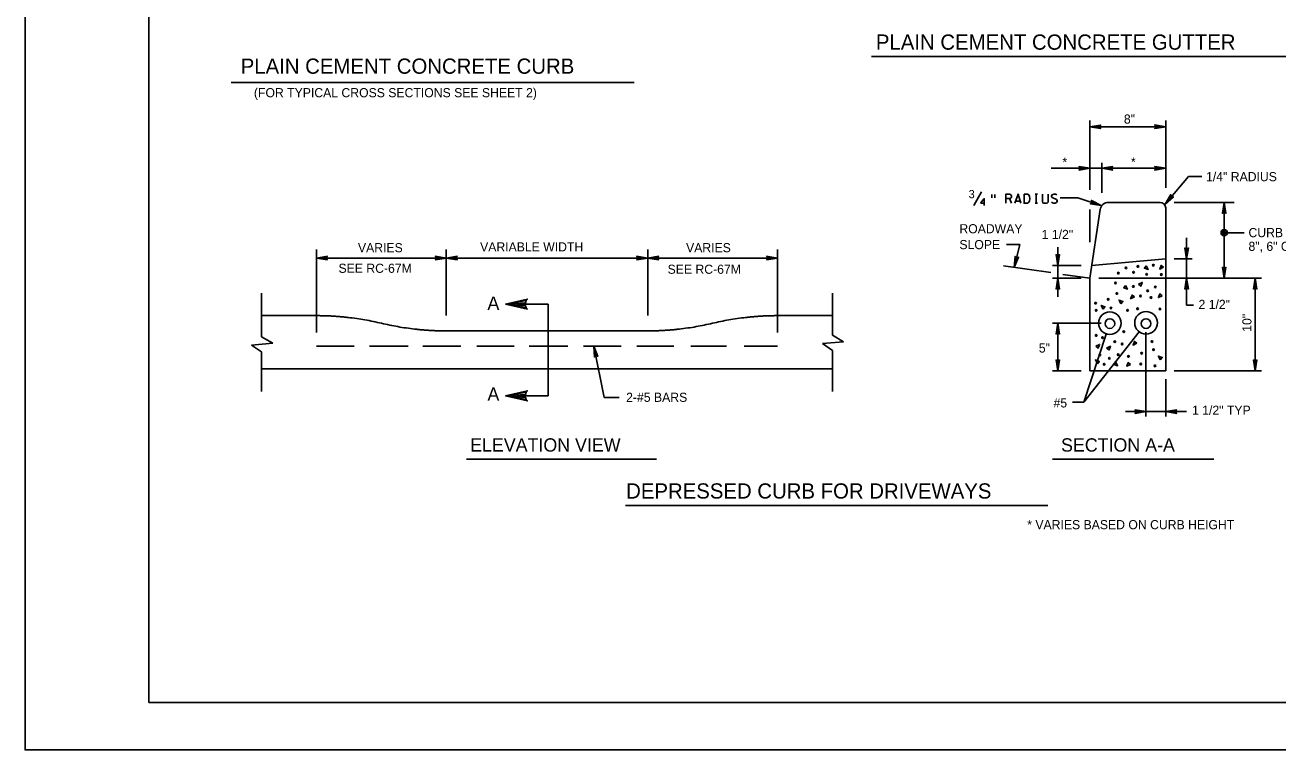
# Model space of a CAD drawing. Extents: x 2092490 to 2102560, y 980575 to 982524.
# Drawn here: x 2096834 to 2098130, y 980575 to 981325 of the extents above; entities that cross this region are included whole.
import ezdxf

# ---------------------------------------------------------------- set-up
doc = ezdxf.new("R2010")
doc.units = 0
for name, color, linetype in [('1', 7, 'Continuous'), ('2', 7, 'Continuous'), ('3', 7, 'Continuous'), ('57', 7, 'Continuous'), ('PLT-BNDY', 7, 'Continuous')]:
    doc.layers.add(name, color=color, linetype=linetype)

msp = doc.modelspace()

# ---------------------------------------------------------------- linework, layer by layer
at = {"layer": '1'}
for p, q in [((2096962.1, 982474.5), (2096962.1, 980624.1)), ((2097929.4, 980934.9), (2097986.7, 981007.6)), ((2097952.7, 981005.3), (2097929.4, 980934.9)), ((2096962.1, 980624.1), (2099540.8, 980624.1))]:
    msp.add_line(p, q, dxfattribs=at)
for centre, radius in [((2097956.4, 981016.5), 11.7), ((2097956.5, 981016.1), 5.02), ((2097993.9, 981016.9), 11.7), ((2097993.9, 981016.1), 5.02)]:
    msp.add_circle(centre, radius, dxfattribs=at)
at = {"layer": '2'}
for p, q in [((2097935.8, 981063.1), (2097946.4, 981134.1)), ((2098008.5, 981141.5), (2097955, 981141.5)), ((2098014.3, 980967.2), (2098014.3, 981135.7)), ((2098014.3, 981083), (2097937.8, 981076.1)), ((2097935.8, 980967.2), (2097935.8, 981063.1)), ((2097078.8, 981002.4), (2097078.8, 981047.6)), ((2097669.4, 981004.1), (2097669.4, 981047.6)), ((2097078.8, 981024.3), (2097135.6, 981024.3)), ((2097612.6, 981024.3), (2097669.4, 981024.3)), ((2097269.9, 981008.5), (2097478.3, 981008.5)), ((2097680.9, 980997.3), (2097669.4, 981004.1)), ((2097068.5, 980993.7), (2097090.4, 980995.7)), ((2097078.8, 980986.8), (2097068.5, 980993.7)), ((2097090.4, 980995.7), (2097078.8, 981002.4)), ((2097135.6, 980992.8), (2097174.7, 980992.8)), ((2097190.5, 980992.8), (2097230.6, 980992.8)), ((2097245.6, 980992.8), (2097284.9, 980992.8)), ((2097301.5, 980992.8), (2097340.2, 980992.8)), ((2097355.6, 980992.8), (2097395.7, 980992.8)), ((2097411.9, 980992.8), (2097450.8, 980992.8)), ((2097467, 980992.8), (2097505.5, 980992.8)), ((2097522.9, 980992.8), (2097559.8, 980992.8)), ((2097578, 980992.8), (2097612.6, 980992.8)), ((2097659.1, 980995.3), (2097680.9, 980997.3)), ((2097669.4, 980988.4), (2097659.1, 980995.3)), ((2097078.8, 980945.8), (2097078.8, 980986.8)), ((2097669.4, 980945.8), (2097669.4, 980988.4)), ((2097078.8, 980969.2), (2097669.4, 980969.2)), ((2098014.3, 980967.2), (2097935.8, 980967.2))]:
    msp.add_line(p, q, dxfattribs=at)
for centre, radius, start, end in [((2097955, 981132.8), 8.72, 90, 171.5668), ((2098008.5, 981135.7), 5.81, 0, 90)]:
    msp.add_arc(centre, radius, start, end, dxfattribs=at)
for points in [[(2097269.9, 981008.5), (2097236.4, 981008.5), (2097169.2, 981024.3), (2097135.6, 981024.3)], [(2097478.3, 981008.5), (2097511.8, 981008.5), (2097579, 981024.3), (2097612.6, 981024.3)]]:
    msp.add_open_spline(points, degree=2, dxfattribs=at)
at = {"layer": '3'}
for p, q in [((2098154.2, 981292.5), (2097710, 981292.5)), ((2097047.3, 981265.6), (2097464.2, 981265.6)), ((2097935.8, 981154.4), (2097935.8, 981226.2)), ((2098014.3, 981156.4), (2098014.3, 981226.2)), ((2098014.3, 981219.8), (2097935.8, 981219.8)), ((2097895.6, 981176.8), (2097948.1, 981176.8)), ((2097948.1, 981151.5), (2097948.1, 981182.4)), ((2097948.1, 981176.8), (2098014.3, 981176.8)), ((2098013.6, 981139.8), (2098037.8, 981168.2)), ((2098037.8, 981168.2), (2098051.5, 981168.2)), ((2097905.2, 981146.3), (2097923.5, 981146.3)), ((2097923.5, 981146.3), (2097947.5, 981138.2)), ((2097935.8, 981100.5), (2097935.8, 981134.1)), ((2098022.9, 981141.5), (2098085, 981141.5)), ((2098074.8, 981063.1), (2098074.8, 981141.5)), ((2098074.8, 981110.1), (2098095.5, 981110.1)), ((2097863.3, 981098), (2097849.4, 981098)), ((2097857.6, 981074.2), (2097863.3, 981098)), ((2097902.7, 981095.2), (2097902.7, 981076.1)), ((2098035.9, 981083), (2098035.9, 981104.9)), ((2097135.6, 981007), (2097135.6, 981092.6)), ((2097269.9, 981083.9), (2097135.6, 981083.9)), ((2097269.9, 981024.3), (2097269.9, 981092.6)), ((2097478.3, 981083.9), (2097269.9, 981083.9)), ((2097478.3, 981024.3), (2097478.3, 981092.6)), ((2097478.3, 981083.9), (2097612.6, 981083.9)), ((2097612.6, 981007), (2097612.6, 981092.6)), ((2098022.9, 981083), (2098041.6, 981083)), ((2098035.9, 981035.2), (2098035.9, 981083)), ((2097895.3, 981068.8), (2097846.5, 981075.7)), ((2097926.9, 981076.1), (2097897.2, 981076.1)), ((2097902.7, 981076.1), (2097902.7, 981043.7)), ((2097926.9, 981063.1), (2097897.2, 981063.1)), ((2097935.8, 981063.1), (2097907.8, 981067)), ((2098113.3, 981063.1), (2097944.9, 981063.1)), ((2098106.8, 980967.2), (2098106.8, 981063.1)), ((2097342.6, 981036.2), (2097375.3, 981036.2)), ((2097375.3, 980941.3), (2097375.3, 981036.2)), ((2098035.9, 981035.2), (2098043, 981035.2)), ((2097947.4, 981016.5), (2097897.2, 981016.5)), ((2097902.7, 981016.5), (2097902.7, 980967.2)), ((2097993.8, 981007.2), (2097993.8, 980920.1)), ((2097433.4, 980939.6), (2097422.6, 980992.8)), ((2097926.9, 980967.2), (2097897.2, 980967.2)), ((2098022.9, 980967.2), (2098113.3, 980967.2)), ((2098014.3, 980958.6), (2098014.3, 980920.1)), ((2097342.6, 980941.3), (2097375.3, 980941.3)), ((2097433.4, 980939.6), (2097448.9, 980939.6)), ((2097917.7, 980934.9), (2097929.4, 980934.9)), ((2097972.6, 980925), (2098014.3, 980925)), ((2098014.3, 980925), (2098035.9, 980925)), ((2097290.9, 980875.9), (2097487.5, 980875.9)), ((2097897, 980875.9), (2098063.9, 980875.9)), ((2097455.3, 980827.9), (2097892.4, 980827.9))]:
    msp.add_line(p, q, dxfattribs=at)
for points in [[(2097946.6, 981218.4), (2097946.2, 981219.2), (2097935.8, 981219.8), (2097946.6, 981218.4), (2097947.1, 981217.9), (2097935.8, 981219.8), (2097946.1, 981220.3), (2097946.5, 981221), (2097935.8, 981219.8), (2097947.1, 981221.5), (2097946.5, 981221)], [(2098003.5, 981221.1), (2098003.9, 981220.3), (2098014.3, 981219.8), (2098003.5, 981221.1), (2098003, 981221.6), (2098014.3, 981219.8), (2098004, 981219.2), (2098003.6, 981218.5), (2098014.3, 981219.8), (2098003, 981218), (2098003.6, 981218.5)], [(2097925.1, 981178.1), (2097925.5, 981177.3), (2097935.8, 981176.8), (2097925.1, 981178.1), (2097924.6, 981178.6), (2097935.8, 981176.8), (2097925.5, 981176.3), (2097925.1, 981175.5), (2097935.8, 981176.8), (2097924.6, 981175), (2097925.1, 981175.5)], [(2097958.9, 981175.4), (2097958.5, 981176.2), (2097948.1, 981176.8), (2097958.9, 981175.4), (2097959.4, 981175), (2097948.1, 981176.8), (2097958.4, 981177.3), (2097958.8, 981178), (2097948.1, 981176.8), (2097959.4, 981178.6), (2097958.8, 981178)], [(2098003.5, 981175.4), (2098003.9, 981176.2), (2098014.3, 981176.8), (2098003.5, 981175.4), (2098003, 981175), (2098014.3, 981176.8), (2098004, 981177.3), (2098003.6, 981178), (2098014.3, 981176.8), (2098003, 981178.6), (2098003.6, 981178)], [(2097815.6, 981138.1), (2097823.7, 981152.3)], [(2097834.5, 981146.1), (2097834.5, 981149.5)], [(2097837.5, 981146.1), (2097837.5, 981149.5)], [(2097848.9, 981140.6), (2097848.9, 981150), (2097852.7, 981150), (2097853.8, 981149.7), (2097854.8, 981148.2), (2097854.8, 981147.3), (2097853.9, 981145.8), (2097852.7, 981145.4), (2097848.9, 981145.4)], [(2097858.3, 981140.6), (2097861.5, 981150), (2097864.5, 981140.6)], [(2097867.8, 981150), (2097871.2, 981150), (2097872.5, 981149.4), (2097873.3, 981147.7), (2097873.7, 981145.6), (2097873.2, 981142.9), (2097872.4, 981141.3), (2097871.2, 981140.6), (2097867.8, 981140.6), (2097867.8, 981150)], [(2097879.3, 981150), (2097881.5, 981150)], [(2097880.4, 981140.6), (2097880.4, 981150)], [(2097886.7, 981150), (2097886.7, 981142.5), (2097887, 981141.2), (2097888.3, 981140.6), (2097890.8, 981140.6), (2097892.2, 981141.2), (2097892.6, 981142.5), (2097892.6, 981150)], [(2097901.6, 981149.4), (2097900.1, 981150), (2097898.4, 981150), (2097896.8, 981149.4), (2097896.1, 981148.2), (2097896.1, 981147.7), (2097896.9, 981146.6), (2097901.2, 981144.4), (2097901.9, 981143.4), (2097901.9, 981142.5), (2097901.2, 981141.3), (2097899.9, 981140.6), (2097898.1, 981140.6), (2097897.3, 981140.9), (2097896.1, 981141.7)], [(2098021.6, 981147.1), (2098020.7, 981147.3), (2098013.6, 981139.8), (2098021.6, 981147.1), (2098022.3, 981147.2), (2098013.6, 981139.8), (2098019.9, 981148), (2098019.5, 981148.8), (2098013.6, 981139.8), (2098019.5, 981149.5), (2098019.5, 981148.8)], [(2097827, 981140.7), (2097823, 981140.7), (2097823, 981141), (2097826.1, 981145.3), (2097826.5, 981145.3), (2097826.5, 981138.2)], [(2097854.8, 981140.6), (2097852.6, 981145.4)], [(2097859.1, 981142.8), (2097863.8, 981142.8)], [(2097879.3, 981140.6), (2097881.5, 981140.6)], [(2097937.8, 981142.9), (2097937.9, 981142), (2097947.5, 981138.2), (2097937.8, 981142.9), (2097937.4, 981143.5), (2097947.5, 981138.2), (2097937.6, 981141), (2097937, 981140.4), (2097947.5, 981138.2), (2097936.3, 981140.1), (2097937, 981140.4)], [(2098073.5, 981130.8), (2098074.3, 981131.2), (2098074.8, 981141.5), (2098073.5, 981130.8), (2098073, 981130.2), (2098074.8, 981141.5), (2098075.3, 981131.2), (2098076.1, 981130.8), (2098074.8, 981141.5), (2098076.6, 981130.2), (2098076.1, 981130.8)], [(2098037.2, 981093.8), (2098036.5, 981093.4), (2098035.9, 981083), (2098037.2, 981093.8), (2098037.7, 981094.3), (2098035.9, 981083), (2098035.4, 981093.4), (2098034.6, 981093.7), (2098035.9, 981083), (2098034.1, 981094.3), (2098034.6, 981093.7)], [(2097146.4, 981082.6), (2097146, 981083.3), (2097135.6, 981083.9), (2097146.4, 981082.6), (2097146.9, 981082.1), (2097135.6, 981083.9), (2097146, 981084.4), (2097146.3, 981085.2), (2097135.6, 981083.9), (2097146.9, 981085.7), (2097146.3, 981085.2)], [(2097259.2, 981085.2), (2097259.6, 981084.5), (2097269.9, 981083.9), (2097259.2, 981085.2), (2097258.7, 981085.7), (2097269.9, 981083.9), (2097259.6, 981083.4), (2097259.2, 981082.6), (2097269.9, 981083.9), (2097258.7, 981082.1), (2097259.2, 981082.6)], [(2097280.7, 981082.6), (2097280.3, 981083.3), (2097269.9, 981083.9), (2097280.7, 981082.6), (2097281.2, 981082.1), (2097269.9, 981083.9), (2097280.3, 981084.4), (2097280.6, 981085.2), (2097269.9, 981083.9), (2097281.2, 981085.7), (2097280.6, 981085.2)], [(2097467.5, 981085.2), (2097467.9, 981084.5), (2097478.3, 981083.9), (2097467.5, 981085.2), (2097467, 981085.7), (2097478.3, 981083.9), (2097468, 981083.4), (2097467.6, 981082.6), (2097478.3, 981083.9), (2097467, 981082.1), (2097467.6, 981082.6)], [(2097489, 981082.6), (2097488.6, 981083.3), (2097478.3, 981083.9), (2097489, 981082.6), (2097489.5, 981082.1), (2097478.3, 981083.9), (2097488.6, 981084.4), (2097489, 981085.2), (2097478.3, 981083.9), (2097489.5, 981085.7), (2097489, 981085.2)], [(2097601.8, 981085.2), (2097602.2, 981084.5), (2097612.6, 981083.9), (2097601.8, 981085.2), (2097601.3, 981085.7), (2097612.6, 981083.9), (2097602.3, 981083.4), (2097601.9, 981082.6), (2097612.6, 981083.9), (2097601.3, 981082.1), (2097601.9, 981082.6)], [(2097861.4, 981084.3), (2097860.6, 981084.1), (2097857.6, 981074.2), (2097861.4, 981084.3), (2097862, 981084.7), (2097857.6, 981074.2), (2097859.5, 981084.3), (2097858.8, 981084.9), (2097857.6, 981074.2), (2097858.5, 981085.6), (2097858.8, 981084.9)], [(2097904.1, 981086.8), (2097903.3, 981086.4), (2097902.7, 981076.1), (2097904.1, 981086.8), (2097904.5, 981087.4), (2097902.7, 981076.1), (2097902.2, 981086.4), (2097901.4, 981086.8), (2097902.7, 981076.1), (2097900.9, 981087.4), (2097901.4, 981086.8)], [(2098076.2, 981073.8), (2098075.4, 981073.4), (2098074.8, 981063.1), (2098076.2, 981073.8), (2098076.6, 981074.3), (2098074.8, 981063.1), (2098074.3, 981073.4), (2098073.5, 981073.8), (2098074.8, 981063.1), (2098073, 981074.3), (2098073.5, 981073.8)], [(2097901.4, 981052.3), (2097902.1, 981052.7), (2097902.7, 981063.1), (2097901.4, 981052.3), (2097900.9, 981051.8), (2097902.7, 981063.1), (2097903.2, 981052.7), (2097904, 981052.4), (2097902.7, 981063.1), (2097904.5, 981051.8), (2097904, 981052.4)], [(2098034.5, 981052.3), (2098035.3, 981052.7), (2098035.9, 981063.1), (2098034.5, 981052.3), (2098034.1, 981051.8), (2098035.9, 981063.1), (2098036.4, 981052.7), (2098037.2, 981052.4), (2098035.9, 981063.1), (2098037.7, 981051.8), (2098037.2, 981052.4)], [(2098105.5, 981052.3), (2098106.3, 981052.7), (2098106.8, 981063.1), (2098105.5, 981052.3), (2098105, 981051.8), (2098106.8, 981063.1), (2098107.3, 981052.7), (2098108.1, 981052.4), (2098106.8, 981063.1), (2098108.6, 981051.8), (2098108.1, 981052.4)], [(2097352.7, 981032.3), (2097351.9, 981034.6), (2097331.3, 981036.2), (2097352.7, 981032.3), (2097353.8, 981031), (2097331.3, 981036.2), (2097351.9, 981037.7), (2097352.7, 981039.9), (2097331.3, 981036.2), (2097353.8, 981041.4), (2097352.7, 981039.9)], [(2097901.4, 981005.7), (2097902.1, 981006.1), (2097902.7, 981016.5), (2097901.4, 981005.7), (2097900.9, 981005.2), (2097902.7, 981016.5), (2097903.2, 981006.1), (2097904, 981005.8), (2097902.7, 981016.5), (2097904.5, 981005.2), (2097904, 981005.8)], [(2097423.4, 980982), (2097424.1, 980982.6), (2097422.6, 980992.8), (2097423.4, 980982), (2097423.1, 980981.4), (2097422.6, 980992.8), (2097425.1, 980982.8), (2097426, 980982.6), (2097422.6, 980992.8), (2097426.6, 980982.1), (2097426, 980982.6)], [(2097904.1, 980977.9), (2097903.3, 980977.5), (2097902.7, 980967.2), (2097904.1, 980977.9), (2097904.5, 980978.5), (2097902.7, 980967.2), (2097902.2, 980977.5), (2097901.4, 980977.9), (2097902.7, 980967.2), (2097900.9, 980978.5), (2097901.4, 980977.9)], [(2098108.2, 980977.9), (2098107.4, 980977.5), (2098106.8, 980967.2), (2098108.2, 980977.9), (2098108.6, 980978.5), (2098106.8, 980967.2), (2098106.3, 980977.5), (2098105.5, 980977.9), (2098106.8, 980967.2), (2098105, 980978.5), (2098105.5, 980977.9)], [(2097352.7, 980937.5), (2097351.9, 980939.7), (2097331.3, 980941.3), (2097352.7, 980937.5), (2097353.8, 980936.1), (2097331.3, 980941.3), (2097351.9, 980942.8), (2097352.7, 980945), (2097331.3, 980941.3), (2097353.8, 980946.5), (2097352.7, 980945)], [(2097983, 980926.4), (2097983.4, 980925.6), (2097993.8, 980925), (2097983, 980926.4), (2097982.5, 980926.8), (2097993.8, 980925), (2097983.4, 980924.5), (2097983.1, 980923.7), (2097993.8, 980925), (2097982.5, 980923.2), (2097983.1, 980923.7)], [(2098025, 980923.7), (2098024.6, 980924.5), (2098014.3, 980925), (2098025, 980923.7), (2098025.5, 980923.2), (2098014.3, 980925), (2098024.6, 980925.5), (2098025, 980926.3), (2098014.3, 980925), (2098025.5, 980926.8), (2098025, 980926.3)]]:
    msp.add_lwpolyline(points, dxfattribs=at)
for radius in [3.28, 1.64]:
    msp.add_circle((2098074.8, 981110.1), radius, dxfattribs=at)
at = {"layer": '57'}
for points in [[(2097994.1, 981075.8), (2097992.2, 981073.3), (2097996, 981071.9)], [(2098012, 981074.3), (2098009.5, 981076.3), (2098008.1, 981072.4)], [(2097972.8, 981055.6), (2097970.8, 981053.1), (2097974.7, 981051.7)], [(2097986.1, 981056.7), (2097988.6, 981054.8), (2097990, 981058.7)], [(2097981.9, 981043.7), (2097979.4, 981045.6), (2097978, 981041.7)], [(2098010.6, 981044.9), (2098008.1, 981046.8), (2098006.8, 981043)], [(2097949.4, 981031.1), (2097951.4, 981033.5), (2097947.5, 981034.9)], [(2097968, 981036.5), (2097970, 981039), (2097966.1, 981040.4)], [(2097942, 980992.7), (2097944.5, 980990.8), (2097945.9, 980994.6)], [(2097953.1, 980990.7), (2097955.6, 980988.8), (2097957, 980992.6)], [(2097984.4, 980995.7), (2097981.9, 980997.7), (2097980.5, 980993.8)], [(2097943.6, 980974.5), (2097945.5, 980977), (2097941.6, 980978.4)], [(2098008.7, 980978.5), (2098010.7, 980981), (2098006.8, 980982.4)], [(2097962.6, 980976.2), (2097960.6, 980973.8), (2097964.5, 980972.4)], [(2097978, 980973.9), (2097975.5, 980975.8), (2097974.2, 980971.9)]]:
    msp.add_lwpolyline(points, close=True, dxfattribs=at)
for centre in [(2097965.3, 981068.3), (2097973.1, 981073.7), (2097981, 981069.2), (2097985.5, 981075.2), (2098001.5, 981076.5), (2097962.3, 981058.1), (2097980.7, 981054.5), (2097994.6, 981067.1), (2098009.8, 981066.8), (2097963.7, 981047.2), (2097988.2, 981044.7), (2097995.6, 981050), (2097999, 981043), (2098003.5, 981053.9), (2097941.7, 981037.2), (2097942.3, 981029.7), (2097954.8, 981041.1), (2097957.7, 981032.2), (2097974.8, 981029.7), (2097985.1, 981031.4), (2098008.4, 981031.2), (2097942.3, 981003.8), (2097970.9, 981007.7), (2097948.9, 981001.6), (2097961.6, 980997.4), (2097969.2, 980995), (2098000, 980997.5), (2097946.1, 980983.7), (2097956, 980980.2), (2097965.1, 980983.9), (2097975.7, 980982.2), (2097989.3, 980985.4), (2098001.7, 980989.1), (2097950.6, 980974), (2097988.5, 980974.3), (2098003.2, 980972.3)]:
    msp.add_circle(centre, 0.842, dxfattribs=at)
at = {"layer": 'PLT-BNDY'}
msp.add_lwpolyline([(2096834.1, 982523.7), (2099593.3, 982523.7), (2099593.3, 980574.9), (2096834.1, 980574.9)], close=True, dxfattribs=at)

# ---------------------------------------------------------------- texts
at = {"layer": '1'}
msp.add_text('3', height=8.5, dxfattribs=at).set_placement((2097810.3, 981145.8))
at = {"layer": '3'}
for s, height, p in [('PLAIN CEMENT CONCRETE GUTTER', 15.748, (2097714.4, 981299.5)), ('PLAIN CEMENT CONCRETE CURB', 15.748, (2097057.2, 981274.6)), ('(FOR TYPICAL CROSS SECTIONS SEE SHEET 2)', 9.449, (2097070.9, 981250.3)), ('8"', 9.45, (2097971, 981223)), ('*', 9.45, (2097907.4, 981178.4)), ('*', 9.45, (2097978.3, 981178.7)), ('1/4" RADIUS', 9.449, (2098056, 981163.4)), ('ROADWAY', 9.45, (2097800.8, 981109.5)), ('1 1/2"', 9.45, (2097885.9, 981103.6)), ('VARIES', 9.45, (2097178.5, 981089.9)), ('VARIABLE WIDTH', 9.449, (2097304.9, 981090.7)), ('VARIES', 9.45, (2097518, 981089.9)), ('SLOPE', 9.45, (2097800.8, 981093.1)), ('SEE RC-67M', 9.45, (2097158.4, 981068.6)), ('SEE RC-67M', 9.45, (2097498.9, 981067.6)), ('A', 13.8, (2097312.5, 981030.3)), ('2 1/2"', 9.45, (2098048.2, 981031.2)), ('5"', 9.45, (2097883, 980986.1)), ('A', 13.8, (2097312.5, 980936.3)), ('2-#5 BARS', 9.45, (2097456, 980935.1)), ('#5', 9.45, (2097898.2, 980929.3)), ('1 1/2" TYP', 9.45, (2098041.5, 980921.7)), ('ELEVATION VIEW', 13.78, (2097294.6, 980883.6)), ('SECTION A-A', 13.78, (2097906, 980883.6)), ('DEPRESSED CURB FOR DRIVEWAYS', 15.748, (2097456, 980835)), ('* VARIES BASED ON CURB HEIGHT', 9.449, (2097871, 980803.3))]:
    msp.add_text(s, height=height, dxfattribs=at).set_placement(p)
for s, height, rotation, p in [('CURB HEIGHT', 9.449, 360, (2098099.9, 981105.5)), ('8", 6" OR 4"', 9.449, 360, (2098099.9, 981091.3)), ('10"', 9.45, 90, (2098103, 981007.6))]:
    msp.add_text(s, height=height, rotation=rotation, dxfattribs=at).set_placement(p)

doc.saveas('drawing.dxf')
